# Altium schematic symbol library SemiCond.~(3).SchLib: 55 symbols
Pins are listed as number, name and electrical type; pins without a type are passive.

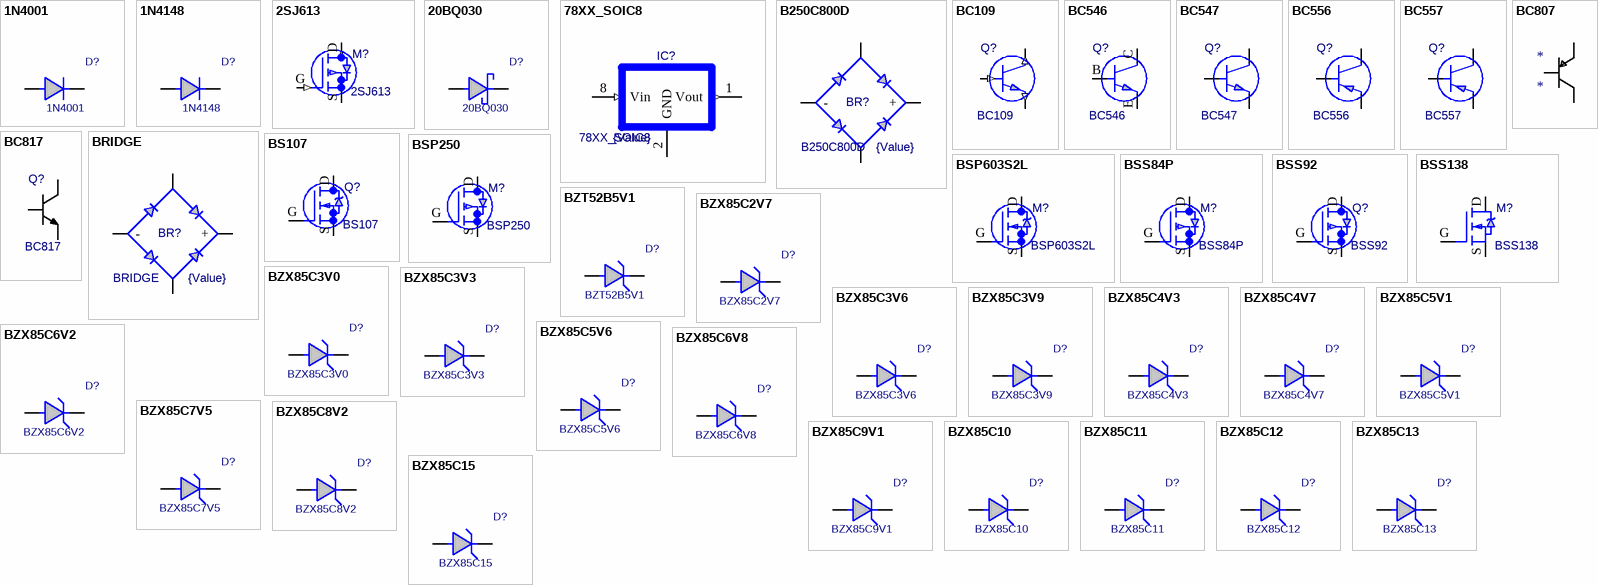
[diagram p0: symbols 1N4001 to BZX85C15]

## 1N4001
designator D?
footprint DO 41 (400MILS) larger pads
pins: A, K

## 1N4148
designator D?
footprint MELF3517N_DIO (MELF Diode, 2-Leads, Body 3,5x1,7mm, IPC Medium Density); pin to pad A>2 K>1
footprint DO 35 (300MILS)
pins: A, K

## 2SJ613
designator M?
Value: {Value}
footprint _SOT89_2SJ613(Primary)
pins: D (out), D2 (out) hidden, G (in), S (power)

## 20BQ030
designator D?
footprint DO-214AA (SMB) (Molded Diode, 2-Leads, Body 4,4x3,6mm, IPC Medium Density); pin to pad A>2 K>1
pins: A, K

## 78XX_SOIC8
designator IC?  value {Value}
footprint SO8R
pins: 1 Vout (out), 2 GND (power), 3 GND (power), 4 hidden, 5 hidden, 6 GND (power), 7 GND (power), 8 Vin (in)

## B250C800D
designator BR?  value {Value}
footprint DIP4M-GREZ
pins: AC1, AC2, GND -, PLUS +

## BC109
designator Q?
Value: {Value}
footprint _TO18_BC109(Primary)
pins: B (in), C (out), E (out)

## BC546
designator Q?
Value: {Value}
footprint TO-92; pin to pad B>2 C>1 E>3
pins: B, C, E

## BC547
designator Q?
Value: {Value}
footprint TO-92; pin to pad 1>3 3>1
pins: 1, 2, 3

## BC556
designator Q?
Value: {Value}
footprint TO-92; pin to pad B>2 C>1 E>3
pins: B, C, E

## BC557
designator Q?
Value: {Value}
footprint TO-92; pin to pad B>2 C>1 E>3
pins: B, C, E

## BC807
designator *
footprint bc807 (SOT23, 3-Leads, Body 2.73x2.40mm, Pitch 0.95mm, IPC Medium Density)
footprint Model Name (Footprint not found); pin to pad B>1 C>3 E>2
pins: B, C, E

## BC817
designator Q?
Value: {Value}
footprint SOT23; pin to pad B>1 C>3 E>2
pins: B, C, E

## BRIDGE
designator BR?  value {Value}
footprint BRIDGE
pins: 1, 2 +, 3, 4 -

## BS107
designator Q?
Value: {Value}
footprint TO-92; pin to pad D>1 G>2 S>3
pins: D, G, S

## BSP250
designator M?
Value: {Value}
footprint _SOT223_BSP250(Primary)
pins: D, DD hidden, G, S

## BSP603S2L
designator M?
Value: {Value}
footprint _SOT223_BSP603S2L(Primary)
pins: D, DD hidden, G, S

## BSS84P
designator M?
Value: {Value}
footprint SOT23; pin to pad D>3 G>1 S>2
pins: D, G, S

## BSS92
designator Q?
Value: {Value}
footprint TO-92; pin to pad D>3 G>2 S>1
pins: D, G, S

## BSS138
designator M?
Value: {Value}
footprint SOT23-BSS138; pin to pad D>3 G>1 S>2
pins: D, G, S

## BZT52B5V1
designator D?
footprint SOD-123
pins: 1, 2

## BZX85C2V7
designator D?
footprint DO 35 (300MILS)
pins: A, K

## BZX85C3V0
designator D?
footprint DO 35 (300MILS)
pins: A, K

## BZX85C3V3
designator D?
footprint DO 35 (300MILS)
pins: A, K

## BZX85C3V6
designator D?
footprint DO 35 (300MILS)
pins: A, K

## BZX85C3V9
designator D?
footprint DO 35 (300MILS)
pins: A, K

## BZX85C4V3
designator D?
footprint DO 35 (300MILS)
pins: A, K

## BZX85C4V7
designator D?
footprint DO 35 (300MILS)
pins: A, K

## BZX85C5V1
designator D?
footprint DO 35 (300MILS)
pins: A, K

## BZX85C5V6
designator D?
footprint DO 35 (300MILS)
pins: A, K

## BZX85C6V2
designator D?
footprint DO 35 (300MILS)
pins: A, K

## BZX85C6V8
designator D?
footprint DO 35 (300MILS)
pins: A, K

## BZX85C7V5
designator D?
footprint DO 35 (300MILS)
pins: A, K

## BZX85C8V2
designator D?
footprint DO 35 (300MILS)
pins: A, K

## BZX85C9V1
designator D?
footprint DO 35 (300MILS)
pins: A, K

## BZX85C10
designator D?
footprint DO 35 (300MILS)
pins: A, K

## BZX85C11
designator D?
footprint DO 35 (300MILS)
pins: A, K

## BZX85C12
designator D?
footprint DO 35 (300MILS)
pins: A, K

## BZX85C13
designator D?
footprint DO 35 (300MILS)
pins: A, K

## BZX85C15
designator D?
footprint DO 35 (300MILS)
pins: A, K

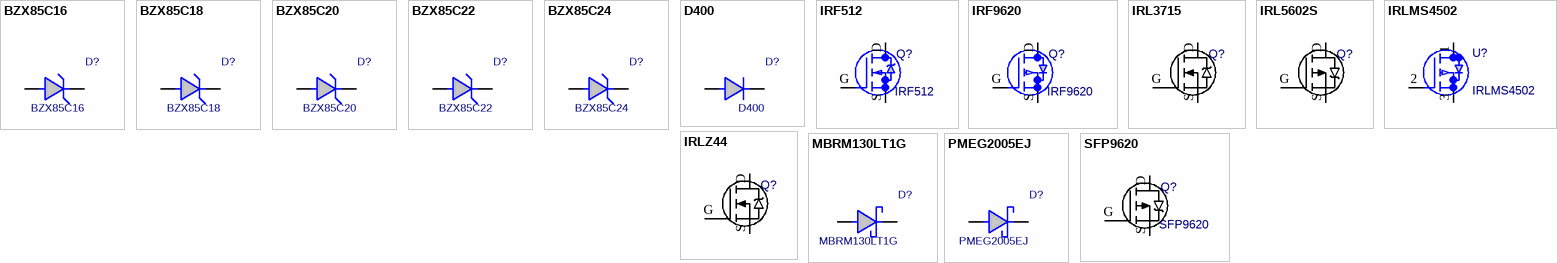
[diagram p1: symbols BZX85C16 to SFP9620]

## BZX85C16
designator D?
footprint DO 35 (300MILS)
pins: A, K

## BZX85C18
designator D?
footprint DO 35 (300MILS)
pins: A, K

## BZX85C20
designator D?
footprint DO 35 (300MILS)
pins: A, K

## BZX85C22
designator D?
footprint DO 35 (300MILS)
pins: A, K

## BZX85C24
designator D?
footprint DO 35 (300MILS)
pins: A, K

## D400
designator D?
footprint D400
pins: 1, 2

## IRF512
designator Q?
Value: {Value}
footprint TO-220AB vertical
footprint TO-220AB horizontal
footprint TO-220AB vertical + HS
footprint TO-220AB vertical + HS2
pins: D, G, S

## IRF9620
designator Q?
Value: {Value}
footprint TO-220AB vertical
footprint TO-220AB horizontal
footprint TO-220AB vertical + HS
footprint TO-220AB vertical + HS2
pins: D, G, S

## IRL3715
designator Q?
HEX-FET Vdss=20V, Id=50A, Rdson=0.011R; Value: {Value}
footprint D2-PAK (D2-PAK, 3-Pads, Body 10,2x10,5mm (max), IPC Medium Density); pin to pad D>2 G>1 S>3
pins: D, G, S

## IRL5602S
designator Q?
HEX-FET Vdss=-20V, Id=-24A, Rdson=0.024R; Value: {Value}
footprint D2-PAK (D2-PAK, 3-Pads, Body 10,2x10,5mm (max), IPC Medium Density); pin to pad D>2 G>1 S>3
pins: D, G, S

## IRLMS4502
designator U?
Value: {Value}
footprint _MICRO6_IRLMS4502(Primary)
pins: 1 D, 2 G, 3 S, 4 hidden, 5 hidden, 6 hidden

## IRLZ44
designator Q?
HEX-FET Vdss=60V, Id=35A, Rdson=0.04R; Value: {Value}
footprint D2-PAK (D2-PAK, 3-Pads, Body 10,2x10,5mm (max), IPC Medium Density); pin to pad D>2 G>1 S>3
pins: D, G, S

## MBRM130LT1G
designator D?
footprint POWERMITE
pins: 1, 2

## PMEG2005EJ
designator D?
footprint SOD-323F
pins: 1, 2

## SFP9620
designator Q?
Value: {Value}
footprint TO-220AB horizontal
footprint TO-220AB vertical
footprint TO-220AB vertical + HS
footprint TO-220AB vertical + HS2
pins: D, G, S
